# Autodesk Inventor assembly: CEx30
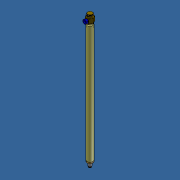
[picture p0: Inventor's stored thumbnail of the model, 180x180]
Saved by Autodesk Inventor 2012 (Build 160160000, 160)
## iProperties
Created: 2013-10
Part Number: CEx30
Document SubType Name: Assembly
Designer: Admin
Translation Standard: STEP AP214IS
FileName: CE430.STEP
PreProcessor: SolidWorks 2009
PostProcessor: Build: 160, Release: 2012 RTM - Date: Tue 03/01/2011
Sent Units: millimeter
Uncertainty: 1e-05
Author: Admin
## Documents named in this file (8)
- C:\Andys Backup Data\ANDY'S INVENTOR\INVENTOR LIBRARIES\PARTS LIBRARY\HYDRAULIC VERTICAL ADJUSTMENT\27.9001Telescoping Twin Leg System\SUBCOMPONENTS\CEx30 cylinder\CEx30.iam
- C:\Andys Backup Data\ANDY'S INVENTOR\INVENTOR LIBRARIES\PARTS LIBRARY\HYDRAULIC VERTICAL ADJUSTMENT\27.9001Telescoping Twin Leg System\SUBCOMPONENTS\CEx30 cylinder\655.00001 14MM CX  BUSHING.ipt
- C:\Andys Backup Data\ANDY'S INVENTOR\INVENTOR LIBRARIES\PARTS LIBRARY\HYDRAULIC VERTICAL ADJUSTMENT\27.9001Telescoping Twin Leg System\SUBCOMPONENTS\CEx30 cylinder\H51-0005 CE & CS RODS (8MM R-RING)_651-00503G.ipt
- C:\Andys Backup Data\ANDY'S INVENTOR\INVENTOR LIBRARIES\PARTS LIBRARY\HYDRAULIC VERTICAL ADJUSTMENT\27.9001Telescoping Twin Leg System\SUBCOMPONENTS\CEx30 cylinder\GROOVED 16MM CYLINDER TUBES_653-01102.ipt
- C:\Andys Backup Data\ANDY'S INVENTOR\INVENTOR LIBRARIES\PARTS LIBRARY\HYDRAULIC VERTICAL ADJUSTMENT\27.9001Telescoping Twin Leg System\SUBCOMPONENTS\CEx30 cylinder\D67-00554 14MM CE C-HEAD ASSY.iam
- C:\Andys Backup Data\ANDY'S INVENTOR\INVENTOR LIBRARIES\PARTS LIBRARY\HYDRAULIC VERTICAL ADJUSTMENT\27.9001Telescoping Twin Leg System\SUBCOMPONENTS\CEx30 cylinder\662-00001 TRANSPORT SCREW.ipt
- C:\Andys Backup Data\ANDY'S INVENTOR\INVENTOR LIBRARIES\PARTS LIBRARY\HYDRAULIC VERTICAL ADJUSTMENT\27.9001Telescoping Twin Leg System\SUBCOMPONENTS\CEx30 cylinder\657-00006 14MM CX PISTON ASSEMBLY.iam
- C:\Andys Backup Data\ANDY'S INVENTOR\INVENTOR LIBRARIES\PARTS LIBRARY\HYDRAULIC VERTICAL ADJUSTMENT\27.9001Telescoping Twin Leg System\SUBCOMPONENTS\CEx30 cylinder\98541A405 SNAP RING.ipt
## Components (7 placed, 7 different names)
1. 655.00001 14MM CX  BUSHING:1
2. H51-0005 CE & CS RODS (8MM R-RING)_651-00503G:1
3. GROOVED 16MM CYLINDER TUBES_653-01102:1
4. D67-00554 14MM CE C-HEAD ASSY:1 [sub-assembly] — Mate:1, Mate:2
5. 662-00001 TRANSPORT SCREW:1 — Angle:1
6. 657-00006 14MM CX PISTON ASSEMBLY:1 [sub-assembly]
7. 98541A405 SNAP RING:1 — Mate:1, Mate:2, Angle:1
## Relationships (3: Mate 2, Angle 1)
- Mate:1: D67-00554 14MM CE C-HEAD ASSY:1 ↔ 98541A405 SNAP RING:1
- Mate:2: D67-00554 14MM CE C-HEAD ASSY:1 ↔ 98541A405 SNAP RING:1
- Angle:1: 662-00001 TRANSPORT SCREW:1 ↔ 98541A405 SNAP RING:1
